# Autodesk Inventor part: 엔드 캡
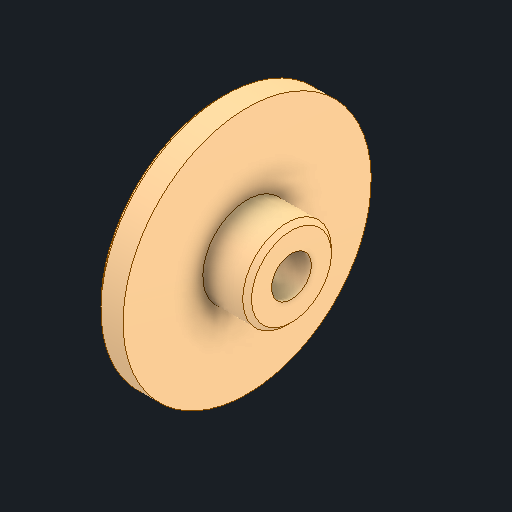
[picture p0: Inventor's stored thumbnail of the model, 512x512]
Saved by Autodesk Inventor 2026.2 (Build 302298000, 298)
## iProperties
Created: 2025-11
Part Number: 엔드 캡
Material: 강철, 연강
Document SubType Name: Modeling
Designer: PC2-07
Density: 7.85 g/cm^3
Appearance: 기본값
Author: jhkim
Sending System: Autodesk Inventor 2026
Preprocessor: ST-DEVELOPER v20.1
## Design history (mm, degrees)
feature "솔리드1"
node "솔리드2"
